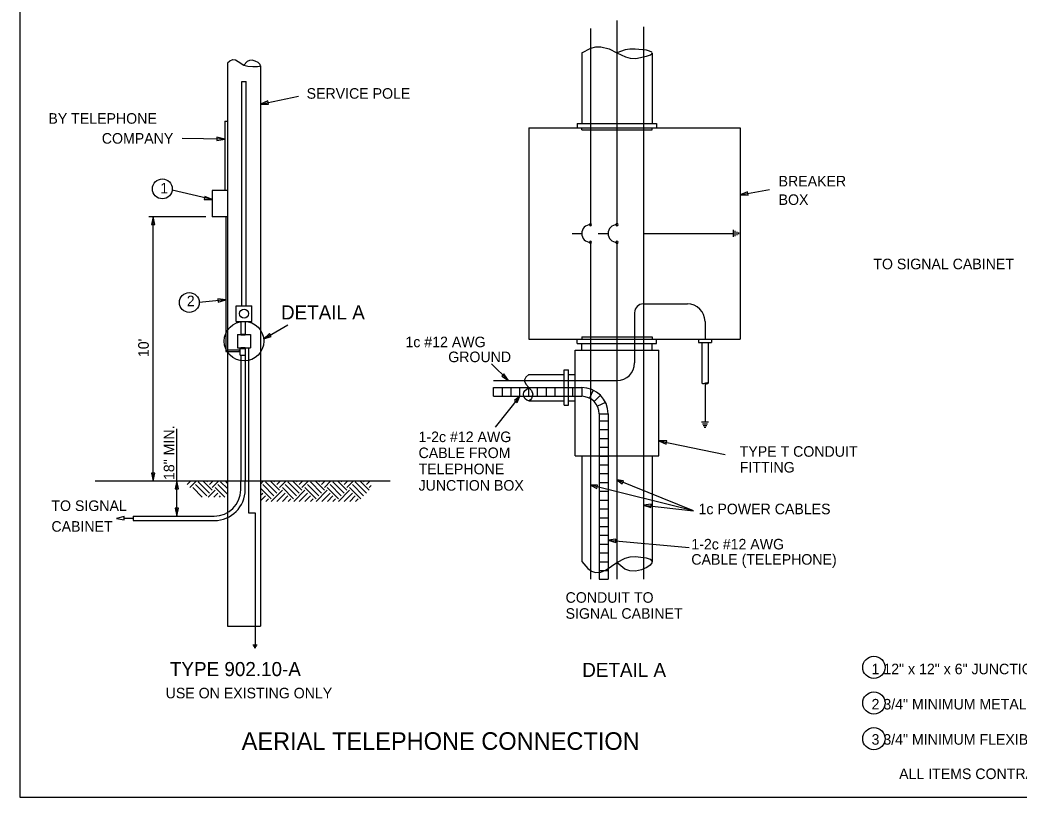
# Model space of a CAD drawing. Extents: x -439.1 to -407.9, y -458.1 to -436.2.
# Drawn here: x -439.11 to -424.94, y -458.05 to -447.02 of the extents above; entities that cross this region are included whole.
import ezdxf

# ---------------------------------------------------------------- set-up
doc = ezdxf.new("R2010")
doc.units = 0
doc.layers.add('Draft_Named_Boundary', color=7, linetype='Continuous')
doc.layers.add('Level 4', color=7, linetype='Continuous')

msp = doc.modelspace()

# ---------------------------------------------------------------- linework, layer by layer
at = {"layer": 'Draft_Named_Boundary'}
msp.add_lwpolyline([(-439.109, -458.051), (-407.859, -458.051), (-407.859, -437.676), (-439.109, -437.676)], close=True, dxfattribs=at)
at = {"layer": 'Level 4'}
for p, q in [((-430.64, -447.026), (-430.64, -449.925)), ((-431.015, -447.14), (-431.015, -449.925)), ((-430.265, -447.117), (-430.265, -454.956)), ((-431.14, -447.487), (-431.14, -448.487)), ((-430.14, -447.488), (-430.14, -448.487)), ((-436.165, -447.63), (-436.165, -453.563)), ((-435.696, -447.669), (-435.696, -453.563)), ((-435.962, -451.079), (-435.962, -447.892)), ((-435.962, -447.892), (-435.899, -447.892)), ((-435.899, -451.079), (-435.899, -447.892)), ((-435.696, -448.212), (-435.156, -448.101)), ((-436.204, -448.457), (-436.165, -448.457)), ((-436.204, -448.457), (-436.204, -449.438)), ((-431.89, -448.55), (-428.89, -448.55)), ((-431.89, -448.55), (-431.89, -451.55)), ((-431.203, -448.487), (-430.078, -448.487)), ((-431.203, -448.487), (-431.203, -448.55)), ((-431.14, -448.581), (-431.14, -448.55)), ((-431.14, -448.581), (-430.14, -448.581)), ((-430.14, -448.581), (-430.14, -448.55)), ((-430.078, -448.487), (-430.078, -448.55)), ((-428.89, -448.55), (-428.89, -451.55)), ((-436.204, -448.709), (-436.808, -448.703)), ((-436.384, -449.568), (-436.948, -449.436)), ((-436.384, -449.438), (-436.384, -449.813)), ((-436.165, -449.438), (-436.384, -449.438)), ((-428.89, -449.503), (-428.474, -449.424)), ((-436.471, -449.813), (-437.282, -449.813)), ((-437.219, -453.563), (-437.219, -449.813)), ((-436.165, -449.813), (-436.384, -449.813)), ((-436.188, -449.813), (-436.188, -451.727)), ((-428.99, -450), (-428.99, -450.1)), ((-428.965, -450.012), (-428.965, -450.087)), ((-431.276, -450.05), (-431.14, -450.05)), ((-430.906, -450.05), (-430.765, -450.05)), ((-430.265, -450.05), (-428.99, -450.05)), ((-428.94, -450.025), (-428.94, -450.075)), ((-428.915, -450.037), (-428.915, -450.062)), ((-431.015, -450.175), (-431.015, -454.956)), ((-430.64, -450.175), (-430.64, -454.956)), ((-436.188, -450.993), (-436.566, -451.03)), ((-436.04, -451.079), (-435.821, -451.079)), ((-436.04, -451.298), (-436.04, -451.079)), ((-435.821, -451.298), (-435.821, -451.079)), ((-430.265, -451.05), (-429.64, -451.05)), ((-436.04, -451.298), (-435.821, -451.298)), ((-435.978, -451.298), (-435.978, -451.481)), ((-435.915, -451.298), (-435.915, -451.481)), ((-430.39, -451.175), (-430.39, -451.888)), ((-435.651, -451.548), (-435.31, -451.348)), ((-429.39, -451.3), (-429.39, -451.55)), ((-436.024, -451.485), (-435.837, -451.485)), ((-436.024, -451.485), (-436.024, -451.673)), ((-435.981, -451.481), (-435.911, -451.481)), ((-435.981, -451.481), (-435.981, -451.485)), ((-435.978, -451.487), (-435.978, -451.485)), ((-435.978, -451.487), (-435.915, -451.487)), ((-435.915, -451.487), (-435.915, -451.485)), ((-435.911, -451.481), (-435.911, -451.485)), ((-435.837, -451.485), (-435.837, -451.673)), ((-431.89, -451.55), (-428.89, -451.55)), ((-431.203, -451.612), (-431.203, -451.55)), ((-431.14, -451.519), (-430.14, -451.519)), ((-431.14, -451.519), (-431.14, -451.55)), ((-430.14, -451.519), (-430.14, -451.55)), ((-430.078, -451.612), (-430.078, -451.55)), ((-429.484, -451.55), (-429.484, -451.597)), ((-429.296, -451.55), (-429.296, -451.597)), ((-436.165, -451.704), (-435.993, -451.704)), ((-436.024, -451.673), (-435.837, -451.673)), ((-435.993, -451.731), (-435.993, -451.7)), ((-435.993, -451.7), (-435.989, -451.7)), ((-435.989, -451.731), (-435.989, -451.7)), ((-435.989, -451.704), (-435.983, -451.704)), ((-435.983, -451.682), (-435.909, -451.682)), ((-435.983, -451.776), (-435.983, -451.682)), ((-435.981, -451.676), (-435.981, -451.673)), ((-435.981, -451.676), (-435.911, -451.676)), ((-435.978, -451.671), (-435.915, -451.671)), ((-435.978, -451.671), (-435.978, -451.673)), ((-435.978, -451.682), (-435.978, -451.676)), ((-435.915, -451.671), (-435.915, -451.673)), ((-435.915, -451.682), (-435.915, -451.676)), ((-435.911, -451.676), (-435.911, -451.673)), ((-435.909, -451.776), (-435.909, -451.682)), ((-435.874, -451.673), (-435.874, -451.675)), ((-435.874, -451.675), (-435.862, -451.675)), ((-435.868, -451.673), (-435.868, -454.017)), ((-435.862, -451.673), (-435.862, -451.675)), ((-431.234, -451.706), (-430.046, -451.706)), ((-431.234, -453.206), (-431.234, -451.706)), ((-431.203, -451.612), (-430.078, -451.612)), ((-431.14, -451.706), (-431.14, -451.612)), ((-430.14, -451.706), (-430.14, -451.612)), ((-430.046, -453.206), (-430.046, -451.706)), ((-429.484, -451.597), (-429.296, -451.597)), ((-429.437, -451.597), (-429.437, -452.175)), ((-429.343, -451.597), (-429.343, -452.175)), ((-436.188, -451.727), (-435.993, -451.727)), ((-435.993, -451.731), (-435.989, -451.731)), ((-435.989, -451.727), (-435.983, -451.727)), ((-435.983, -451.776), (-435.909, -451.776)), ((-435.978, -451.776), (-435.978, -453.563)), ((-435.915, -451.776), (-435.915, -453.563)), ((-432.18, -452.138), (-432.418, -451.903)), ((-431.39, -452.487), (-431.39, -451.987)), ((-431.39, -451.987), (-431.328, -451.987)), ((-431.328, -452.487), (-431.328, -451.987)), ((-432.39, -452.138), (-430.64, -452.138)), ((-431.89, -452.05), (-431.39, -452.05)), ((-431.328, -452.05), (-431.234, -452.05)), ((-432.39, -452.237), (-431.14, -452.237)), ((-432.39, -452.362), (-432.39, -452.237)), ((-432.265, -452.362), (-432.265, -452.237)), ((-432.14, -452.362), (-432.14, -452.237)), ((-432.015, -452.362), (-432.015, -452.237)), ((-431.89, -452.362), (-431.89, -452.237)), ((-431.765, -452.362), (-431.765, -452.237)), ((-431.64, -452.362), (-431.64, -452.237)), ((-431.515, -452.362), (-431.515, -452.237)), ((-431.39, -452.362), (-431.39, -452.237)), ((-431.265, -452.362), (-431.265, -452.237)), ((-431.14, -452.237), (-431.14, -452.362)), ((-430.976, -452.275), (-431.031, -452.387)), ((-429.39, -452.175), (-429.39, -452.73)), ((-432.39, -452.362), (-431.14, -452.362)), ((-431.89, -452.425), (-431.39, -452.425)), ((-431.328, -452.425), (-431.234, -452.425)), ((-430.875, -452.347), (-430.963, -452.436)), ((-431.39, -452.487), (-431.328, -452.487)), ((-430.803, -452.448), (-430.915, -452.503)), ((-430.89, -452.612), (-430.765, -452.612)), ((-430.89, -452.612), (-430.89, -454.956)), ((-430.89, -452.71), (-430.765, -452.71)), ((-430.765, -452.612), (-430.765, -454.956)), ((-436.885, -454.063), (-436.885, -452.823)), ((-430.89, -452.835), (-430.765, -452.835)), ((-429.34, -452.73), (-429.44, -452.73)), ((-429.353, -452.755), (-429.428, -452.755)), ((-429.365, -452.78), (-429.415, -452.78)), ((-429.378, -452.805), (-429.403, -452.805)), ((-430.89, -452.96), (-430.765, -452.96)), ((-430.046, -452.994), (-429.103, -453.188)), ((-430.89, -453.085), (-430.765, -453.085)), ((-431.234, -453.206), (-430.046, -453.206)), ((-431.14, -453.206), (-431.14, -454.706)), ((-430.89, -453.21), (-430.765, -453.21)), ((-430.14, -453.206), (-430.14, -454.706)), ((-430.89, -453.335), (-430.765, -453.335)), ((-438.04, -453.563), (-433.858, -453.563)), ((-436.735, -453.612), (-436.686, -453.563)), ((-436.699, -453.656), (-436.606, -453.563)), ((-436.381, -453.695), (-436.513, -453.563)), ((-436.46, -453.576), (-436.447, -453.563)), ((-436.421, -453.616), (-436.368, -453.563)), ((-436.381, -453.656), (-436.288, -453.563)), ((-436.165, -453.593), (-436.195, -453.563)), ((-436.165, -453.563), (-436.165, -455.626)), ((-435.977, -453.688), (-435.978, -453.563)), ((-435.915, -453.688), (-435.915, -453.563)), ((-435.696, -453.607), (-435.652, -453.563)), ((-435.696, -453.563), (-435.696, -455.626)), ((-435.426, -453.695), (-435.559, -453.563)), ((-435.506, -453.576), (-435.493, -453.563)), ((-435.466, -453.616), (-435.413, -453.563)), ((-435.426, -453.656), (-435.334, -453.563)), ((-435.108, -453.695), (-435.241, -453.563)), ((-435.188, -453.576), (-435.174, -453.563)), ((-435.148, -453.616), (-435.095, -453.563)), ((-435.108, -453.656), (-435.015, -453.563)), ((-434.79, -453.695), (-434.922, -453.563)), ((-434.869, -453.576), (-434.856, -453.563)), ((-434.83, -453.616), (-434.777, -453.563)), ((-434.79, -453.656), (-434.697, -453.563)), ((-434.472, -453.695), (-434.604, -453.563)), ((-434.551, -453.576), (-434.538, -453.563)), ((-434.511, -453.616), (-434.459, -453.563)), ((-434.472, -453.656), (-434.379, -453.563)), ((-434.153, -453.695), (-434.286, -453.563)), ((-434.233, -453.576), (-434.22, -453.563)), ((-434.193, -453.616), (-434.14, -453.563)), ((-430.89, -453.46), (-430.765, -453.46)), ((-429.555, -453.988), (-430.643, -453.547)), ((-436.523, -453.792), (-436.659, -453.656)), ((-436.46, -453.775), (-436.619, -453.616)), ((-436.421, -453.735), (-436.58, -453.576)), ((-436.438, -453.792), (-436.341, -453.695)), ((-436.205, -453.792), (-436.341, -453.656)), ((-436.165, -453.752), (-436.301, -453.616)), ((-436.165, -453.673), (-436.262, -453.576)), ((-435.546, -453.815), (-435.696, -453.664)), ((-435.506, -453.775), (-435.665, -453.616)), ((-435.466, -453.735), (-435.625, -453.576)), ((-435.544, -453.853), (-435.386, -453.695)), ((-435.227, -453.815), (-435.386, -453.656)), ((-435.188, -453.775), (-435.347, -453.616)), ((-435.148, -453.735), (-435.307, -453.576)), ((-435.225, -453.853), (-435.068, -453.695)), ((-434.909, -453.815), (-435.068, -453.656)), ((-434.869, -453.775), (-435.028, -453.616)), ((-434.83, -453.735), (-434.989, -453.576)), ((-434.907, -453.853), (-434.75, -453.695)), ((-434.591, -453.815), (-434.75, -453.656)), ((-434.551, -453.775), (-434.71, -453.616)), ((-434.511, -453.735), (-434.671, -453.576)), ((-434.589, -453.853), (-434.432, -453.695)), ((-434.273, -453.815), (-434.432, -453.656)), ((-434.233, -453.775), (-434.392, -453.616)), ((-434.193, -453.735), (-434.352, -453.576)), ((-434.153, -453.656), (-434.127, -453.629)), ((-429.555, -453.988), (-431.013, -453.624)), ((-430.89, -453.585), (-430.765, -453.585)), ((-436.358, -453.792), (-436.301, -453.735)), ((-436.278, -453.792), (-436.262, -453.775)), ((-435.696, -453.766), (-435.665, -453.735)), ((-435.696, -453.846), (-435.625, -453.775)), ((-435.623, -453.853), (-435.585, -453.815)), ((-435.464, -453.853), (-435.347, -453.735)), ((-435.384, -453.853), (-435.307, -453.775)), ((-435.305, -453.853), (-435.267, -453.815)), ((-435.146, -453.853), (-435.028, -453.735)), ((-435.066, -453.853), (-434.989, -453.775)), ((-434.987, -453.853), (-434.949, -453.815)), ((-434.828, -453.853), (-434.71, -453.735)), ((-434.748, -453.853), (-434.671, -453.775)), ((-434.669, -453.853), (-434.631, -453.815)), ((-434.509, -453.853), (-434.392, -453.735)), ((-434.43, -453.853), (-434.352, -453.775)), ((-434.35, -453.853), (-434.313, -453.815)), ((-430.89, -453.71), (-430.765, -453.71)), ((-430.89, -453.835), (-430.765, -453.835)), ((-430.89, -453.96), (-430.765, -453.96)), ((-430.265, -453.905), (-429.555, -453.988)), ((-437.63, -454.094), (-437.505, -454.094)), ((-437.505, -454.063), (-436.353, -454.063)), ((-437.505, -454.063), (-437.505, -454.126)), ((-437.505, -454.126), (-436.353, -454.126)), ((-435.868, -454.017), (-435.774, -454.017)), ((-435.774, -454.017), (-435.774, -455.892)), ((-430.89, -454.085), (-430.765, -454.085)), ((-430.89, -454.21), (-430.765, -454.21)), ((-430.89, -454.335), (-430.765, -454.335)), ((-430.765, -454.405), (-429.617, -454.506)), ((-430.89, -454.46), (-430.765, -454.46)), ((-430.89, -454.585), (-430.765, -454.585)), ((-430.89, -454.71), (-430.765, -454.71)), ((-430.89, -454.835), (-430.765, -454.835)), ((-430.89, -454.956), (-430.765, -454.956)), ((-436.165, -455.626), (-435.696, -455.626)), ((-435.806, -455.892), (-435.743, -455.892)), ((-435.797, -455.907), (-435.752, -455.907)), ((-435.788, -455.923), (-435.761, -455.923)), ((-435.779, -455.939), (-435.77, -455.939))]:
    msp.add_line(p, q, dxfattribs=at)
for points in [[(-431.14, -447.487), (-431.01, -447.42), (-430.939, -447.402), (-430.868, -447.399), (-430.75, -447.431), (-430.64, -447.487), (-430.519, -447.544), (-430.451, -447.561), (-430.373, -447.564), (-430.218, -447.535), (-430.162, -447.512), (-430.145, -447.499), (-430.14, -447.487), (-430.146, -447.476), (-430.176, -447.461), (-430.222, -447.448), (-430.381, -447.432), (-430.456, -447.435), (-430.521, -447.445), (-430.64, -447.487)], [(-436.165, -447.629), (-436.131, -447.598), (-436.091, -447.58), (-436.051, -447.585), (-436.012, -447.607), (-435.934, -447.659), (-435.876, -447.675), (-435.806, -447.679), (-435.737, -447.68), (-435.71, -447.677), (-435.696, -447.669), (-435.703, -447.649), (-435.732, -447.624), (-435.773, -447.602), (-435.816, -447.59), (-435.853, -447.594), (-435.884, -447.61), (-435.934, -447.659)], [(-431.89, -452.05), (-431.932, -452.089), (-431.954, -452.138), (-431.934, -452.189), (-431.89, -452.237), (-431.851, -452.281), (-431.835, -452.332), (-431.851, -452.392), (-431.868, -452.414), (-431.89, -452.425), (-431.916, -452.418), (-431.941, -452.396), (-431.959, -452.365), (-431.967, -452.332), (-431.96, -452.302), (-431.941, -452.277), (-431.89, -452.237)], [(-429.437, -452.175), (-429.428, -452.179), (-429.419, -452.182), (-429.405, -452.18), (-429.391, -452.175), (-429.379, -452.17), (-429.364, -452.167), (-429.351, -452.169), (-429.343, -452.175), (-429.35, -452.183), (-429.367, -452.188), (-429.381, -452.185), (-429.391, -452.175)], [(-432.015, -452.362), (-432.365, -452.802)], [(-431.14, -454.706), (-431.054, -454.806), (-431.002, -454.844), (-430.946, -454.864), (-430.87, -454.858), (-430.793, -454.824), (-430.643, -454.722), (-430.521, -454.658), (-430.454, -454.641), (-430.376, -454.634), (-430.224, -454.653), (-430.167, -454.675), (-430.14, -454.706), (-430.143, -454.726), (-430.168, -454.759), (-430.214, -454.791), (-430.292, -454.827), (-430.376, -454.846), (-430.457, -454.841), (-430.526, -454.814), (-430.643, -454.722)]]:
    msp.add_lwpolyline(points, dxfattribs=at)
for points in [[(-435.592, -448.167), (-435.696, -448.212), (-435.583, -448.212)], [(-436.315, -448.731), (-436.204, -448.709), (-436.314, -448.685)], [(-436.497, -449.568), (-436.384, -449.568), (-436.487, -449.523)], [(-428.785, -449.459), (-428.89, -449.503), (-428.777, -449.505)], [(-437.196, -449.924), (-437.219, -449.813), (-437.242, -449.924)], [(-436.296, -451.025), (-436.188, -450.993), (-436.3, -450.979)], [(-435.567, -451.472), (-435.651, -451.548), (-435.544, -451.512)], [(-432.274, -452.077), (-432.18, -452.138), (-432.242, -452.044)], [(-432.055, -452.45), (-432.015, -452.362), (-432.092, -452.421)], [(-429.933, -452.994), (-430.046, -452.994), (-429.942, -453.039)], [(-437.242, -453.452), (-437.219, -453.563), (-437.196, -453.452)], [(-436.862, -453.674), (-436.885, -453.563), (-436.908, -453.674)], [(-430.547, -453.561), (-430.643, -453.547), (-430.565, -453.605)], [(-430.916, -453.624), (-431.013, -453.624), (-430.927, -453.669)], [(-436.908, -453.952), (-436.885, -454.063), (-436.862, -453.952)], [(-430.152, -453.895), (-430.265, -453.905), (-430.158, -453.94)], [(-437.63, -454.07), (-437.74, -454.097), (-437.629, -454.116)], [(-430.653, -454.392), (-430.765, -454.405), (-430.657, -454.438)]]:
    msp.add_lwpolyline(points, close=True, dxfattribs=at)
for centre, radius in [((-437.089, -449.417), 0.141), ((-436.707, -451.03), 0.141), ((-435.93, -451.188), 0.0625), ((-435.93, -451.579), 0.281), ((-426.994, -456.21), 0.158), ((-426.994, -456.715), 0.158), ((-426.994, -457.223), 0.158)]:
    msp.add_circle(centre, radius, dxfattribs=at)
for centre, radius, start, end in [((-431.015, -450.05), 0.125, 90.0001, 269.9999), ((-431.015, -449.925), 0.0156, 0, 180), ((-431.015, -449.925), 0.0156, 180, 0), ((-430.64, -450.05), 0.125, 90.0001, 269.9999), ((-430.64, -449.925), 0.0156, 0, 180), ((-430.64, -449.925), 0.0156, 180, 0), ((-431.015, -450.175), 0.0156, 0, 180), ((-430.64, -450.175), 0.0156, 0, 180), ((-431.015, -450.175), 0.0156, 180, 0), ((-430.64, -450.175), 0.0156, 180, 0), ((-430.265, -451.175), 0.125, 90, 180), ((-429.64, -451.3), 0.25, 0, 90), ((-430.64, -451.888), 0.25, 270, 0), ((-431.14, -452.612), 0.375, 0, 90), ((-431.14, -452.612), 0.25, 0, 90), ((-436.352, -453.688), 0.438, 270, 360), ((-436.352, -453.688), 0.375, 270, 0)]:
    msp.add_arc(centre, radius, start, end, dxfattribs=at)

# ---------------------------------------------------------------- texts
for s, height, p in [('SERVICE POLE', 0.15, (-435.042, -448.137)), ('BY TELEPHONE', 0.15, (-438.706, -448.492)), ('COMPANY', 0.15, (-437.948, -448.775)), ('BREAKER', 0.15, (-428.346, -449.382)), ('1', 0.15, (-437.118, -449.482)), ('BOX', 0.15, (-428.346, -449.645)), ('TO SIGNAL CABINET', 0.15, (-427.002, -450.558)), ('2', 0.15, (-436.742, -451.083)), ('DETAIL A', 0.2, (-435.406, -451.27)), ('1c #12 AWG', 0.15, (-433.64, -451.665)), ('GROUND', 0.15, (-433.033, -451.877)), ('1-2c #12 AWG', 0.15, (-433.454, -453.012)), ('CABLE FROM', 0.15, (-433.454, -453.239)), ('TYPE T CONDUIT', 0.15, (-428.898, -453.22)), ('TELEPHONE', 0.15, (-433.454, -453.468)), ('FITTING', 0.15, (-428.898, -453.444)), ('JUNCTION BOX', 0.15, (-433.454, -453.701)), ('TO SIGNAL', 0.15, (-438.663, -453.99)), ('1c POWER CABLES', 0.15, (-429.482, -454.036)), ('CABINET', 0.15, (-438.663, -454.284)), ('1-2c #12 AWG', 0.15, (-429.584, -454.536)), ('CABLE (TELEPHONE)', 0.15, (-429.584, -454.752)), ('CONDUIT TO', 0.15, (-431.368, -455.293)), ('SIGNAL CABINET', 0.15, (-431.368, -455.52)), ('TYPE 902.10-A', 0.2, (-436.982, -456.334)), ('DETAIL A', 0.2, (-431.132, -456.346)), ('1 12" x 12" x 6" JUNCTION BOX WITH 3/4" TO 1 1/2" KNOCK-OUT IN BOTTOM.', 0.15, (-427.027, -456.308)), ('USE ON EXISTING ONLY', 0.15, (-437.042, -456.65)), ('2 3/4" MINIMUM METAL CONDUIT CONTAINING  1-2c #12 AWG AND 1c #12 AWG.', 0.15, (-427.027, -456.808)), ('AERIAL TELEPHONE CONNECTION', 0.25, (-435.964, -457.381)), ('3 3/4" MINIMUM FLEXIBLE CONDUIT CONTAINING 1-2c #12 AWG AND 1c #12 AWG.', 0.15, (-427.027, -457.308)), ('ALL ITEMS CONTRACTOR FURNISHED AND INSTALLED.', 0.15, (-426.636, -457.796))]:
    msp.add_text(s, height=height, dxfattribs=at).set_placement(p)
for s, p in [("10'", (-437.282, -451.805)), ('18" MIN.', (-436.919, -453.55))]:
    msp.add_text(s, height=0.15, rotation=90, dxfattribs=at).set_placement(p)

doc.saveas('drawing.dxf')
